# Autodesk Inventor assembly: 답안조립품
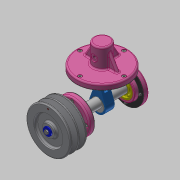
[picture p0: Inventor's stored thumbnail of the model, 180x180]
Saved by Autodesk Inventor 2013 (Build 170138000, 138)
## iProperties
Created: 2020-02
Part Number: 답안조립품
Document SubType Name: Assembly
Designer: Administrator
Author: Administrator
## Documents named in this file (20)
- C:\Users\Administrator\Desktop\600206V1020\답안조립품.iam
- C:\Users\Administrator\Desktop\600206V1020\본체.ipt
- C:\Users\Administrator\Desktop\600206V1020\E-링.ipt
- C:\Users\Administrator\Desktop\600206V1020\V-벨트풀리.ipt
- C:\Users\Administrator\Desktop\600206V1020\개스킷 A.ipt
- C:\Users\Administrator\Desktop\600206V1020\개스킷 B.ipt
- C:\Users\Administrator\Desktop\600206V1020\덮개.ipt
- C:\Users\Administrator\Desktop\600206V1020\뒤커버.ipt
- C:\Users\Administrator\Desktop\600206V1020\링크.ipt
- C:\Users\Administrator\Desktop\600206V1020\베어링 17 x 40 x 12.ipt
- C:\Users\Administrator\Desktop\600206V1020\볼트 M4 x 10.ipt
- C:\Users\Administrator\Desktop\600206V1020\슬라이더.ipt
- C:\Users\Administrator\Desktop\600206V1020\앞커버.ipt
- C:\Users\Administrator\Desktop\600206V1020\오일 실 17 30 8.ipt
- C:\Users\Administrator\Desktop\600206V1020\와셔 4x16.ipt
- C:\Users\Administrator\Desktop\600206V1020\육각 소켓 머리 볼트 M4 x 10.ipt
- C:\Users\Administrator\Desktop\600206V1020\클레비스 핀 6 x 22.ipt
- 클레비스 핀 6 x 22.ipt
- C:\Users\Administrator\Desktop\600206V1020\키 4 x 4 x 25.ipt
- C:\Users\Administrator\Desktop\600206V1020\편심축.ipt
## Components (5 placed, 4 different names)
1. E-링:1
2. V-벨트풀리:1
3. 개스킷 A:1
4. 개스킷 B:1
5. 개스킷 A:2
